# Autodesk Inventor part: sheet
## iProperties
Created: 2007-11
Part Number: sheet
Document SubType Name: Modeling
Designer: Administrateur
Author: Administrateur
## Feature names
1. Extrusion1
2. Extrusion3
3. Hole2
4. Hole3
5. Hole4
6. Hole5
7. Hole6
8. Hole7
9. Hole8
10. Hole11
11. Hole13
12. Hole14
13. Extrusion4
14. Hole15
15. Hole17
16. Hole18
17. Fillet1
